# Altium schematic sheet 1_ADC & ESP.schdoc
size 307 x 218 mm; Symbol: Drawing-Symbol_A4; Device: Drawing-Symbol_A4; @Project Name: Bed Temp Regulation; @Page Count: 4; @Update Date: 2026-02-17; @Create Date: 2026-02-11; @Schematic Name: Schematic Main; @Page No: 1; @Page Name: ADC & ESP; Company: EasyEDA.com; Version: V1.0; Page Size: A4; @Create Time: 12:15:24; @Update Time: 20:09:26; Width: 1170; Height: 825; Region Start: 1; X Region Count: 6; Y Region Count: 4; Blade Width: 10; Title Block Position: 3; @Board Name: Main Board
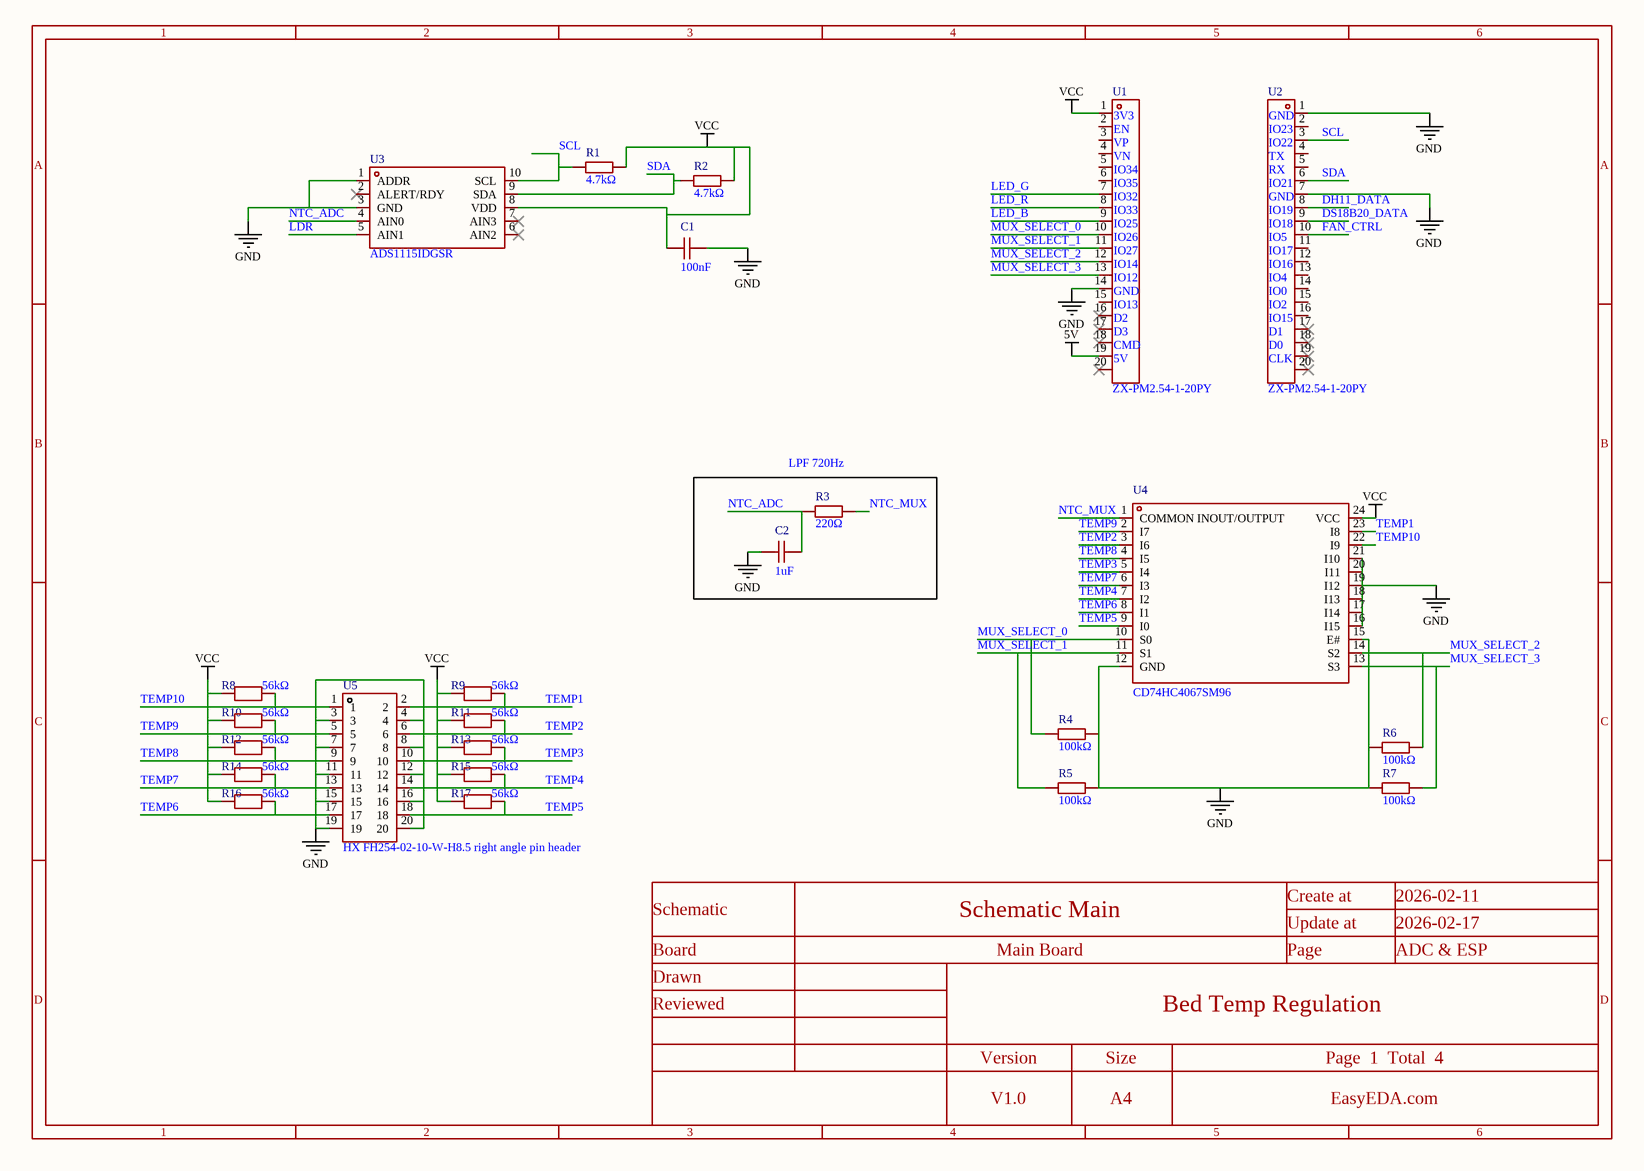
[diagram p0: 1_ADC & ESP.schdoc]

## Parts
C1  100nF  [C0805]
C2  1uF  [C0805]
R1  4.7kΩ  [R0805]
R2  4.7kΩ  [R0805]
R3  220Ω  [R0805]
R4  100kΩ  [R0805]
R5  100kΩ  [R0805]
R6  100kΩ  [R0805]
R7  100kΩ  [R0805]
R8  56kΩ  [R0805]
R9  56kΩ  [R0805]
R10  56kΩ  [R0805]
R11  56kΩ  [R0805]
R12  56kΩ  [R0805]
R13  56kΩ  [R0805]
R14  56kΩ  [R0805]
R15  56kΩ  [R0805]
R16  56kΩ  [R0805]
R17  56kΩ  [R0805]
U1  ZX-PM2.54-1-20PY  [HDR-TH_20P-P2.54-V-F]
U2  ZX-PM2.54-1-20PY  [HDR-TH_20P-P2.54-V-F]
U3  ADS1115IDGSR  [MSOP-10_L3.0-W3.0-P0.50-LS5.0-BL]
U4  CD74HC4067SM96  [SSOP-24_L8.1-W5.3-P0.65-LS7.8-BL]
U5  HX FH254-02-10-W-H8.5 right angle pin header  [HDR-TH_20P-P2.54-H-F-R2-C10-S2.54-W12.7]

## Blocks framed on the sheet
LPF 720Hz: C2 R3

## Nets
5V: U1.19
GND: C1.1 C2.1 R4.2 R5.2 R6.1 R7.1 U1.14 U2.1 U2.7 U3.1(ADDR) U3.3(GND) U4.12(GND) U4.15(E#) U4.16(I15) U4.17(I14) U4.18(I13) U4.19(I12) U4.20(I11) U4.21(I10) U5.3 U5.4 U5.7 U5.8 U5.11 U5.12 U5.15 U5.16 U5.19 U5.20
VCC: C1.2 R1.1 R2.2 R8.1 R9.1 R10.1 R11.1 R12.1 R13.1 R14.1 R15.1 R16.1 R17.1 U1.1 U3.8(VDD) U4.24(VCC)
DH11_DATA: U2.8
DS18B20_DATA: U2.9
FAN_CTRL: U2.10
LDR: U3.5(AIN1)
LED_B: U1.9
LED_G: U1.7
LED_R: U1.8
MUX_SELECT_0: R4.1 U1.10 U4.10(S0)
MUX_SELECT_1: R5.1 U1.11 U4.11(S1)
MUX_SELECT_2: R6.2 U1.12 U4.14(S2)
MUX_SELECT_3: R7.2 U1.13 U4.13(S3)
NTC_ADC: C2.2 R3.1 U3.4(AIN0)
NTC_MUX: R3.2 U4.1(COMMON_INOUT/OUTPUT)
SCL: R1.2 U2.3 U3.10(SCL)
SDA: R2.1 U2.6 U3.9(SDA)
TEMP1: R9.2 U4.23(I8) U5.2
TEMP2: R11.2 U4.3(I6) U5.6
TEMP3: R13.2 U4.5(I4) U5.10
TEMP4: R15.2 U4.7(I2) U5.14
TEMP5: R17.2 U4.9(I0) U5.18
TEMP6: R16.2 U4.8(I1) U5.17
TEMP7: R14.2 U4.6(I3) U5.13
TEMP8: R12.2 U4.4(I5) U5.9
TEMP9: R10.2 U4.2(I7) U5.5
TEMP10: R8.2 U4.22(I9) U5.1

Not connected (* = marked no-connect by the designer): U1 2 3 4 5 6 15 16* 17* 18* 20*; U2 2 4 5 11 12 13 14 15 16 17* 18* 19* 20*; U3 2(ALERT/RDY)* 6(AIN2)* 7(AIN3)*

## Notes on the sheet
- (near U1) 3V3
  EN
  VP
  VN
  IO34
  IO35
  IO32
  IO33
  IO25
  IO26
  IO27
  IO14
  IO12
  GND
  IO13
  D2
  D3
  CMD
  5V
- (near U2) GND
  IO23
  IO22
  TX
  RX
  IO21
  GND
  IO19
  IO18
  IO5
  IO17
  IO16
  IO4
  IO0
  IO2
  IO15
  D1
  D0
  CLK

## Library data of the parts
C1 = CL21B104KCFNNNE: Manufacturer: SAMSUNG(三星); Add into BOM: yes; Tolerance: ±10%; Voltage Rating: 100V; Temperature Coefficient: X7R
C2 = CL21B105KBFNNNE: Manufacturer: SAMSUNG(三星); Add into BOM: yes; Tolerance: ±10%; Voltage Rating: 50V; Temperature Coefficient: X7R
R1 R2 = 0805W8F4701T5E: Manufacturer: UNI-ROYAL(厚声); Add into BOM: yes; Tolerance: ±1%; Temperature Coefficient: ±100ppm/℃
R3 = 0805W8F2200T5E: Manufacturer: UNI-ROYAL(厚声); Add into BOM: yes; Tolerance: ±1%; Power(Watts): 125mW; Voltage-Supply(Max): 150V; Temperature Coefficient: ±100ppm/℃
R4-R7 = 0805W8F1003T5E: Manufacturer: UNI-ROYAL(厚声); Symbol: 0805W8F1003T5E_C149504; Add into BOM: yes; Tolerance: ±1%; Power(Watts): 125mW; Voltage-Supply(Max): 150V; Temperature Coefficient: ±100ppm/℃
R8-R17 = TC0525B5602T5G: Manufacturer: UNI-ROYAL(厚声); Add into BOM: yes; Tolerance: ±0.1%; Power(Watts): 125mW; Voltage-Supply(Max): 150V; Temperature Coefficient: ±25ppm/℃
U1 U2 = ZX-PM2.54-1-20PY: Manufacturer: Megastar(兆星); Add into BOM: yes; Holes Structure: 1x20P; Pitch: 2.54mm; Circular Hole / Square Hole: Square Hole; Number of Positions: 20P; Current Rating: 3A; Holes Direction: Top; PIN Length: 3.2mm
U3 = ADS1115IDGSR: Manufacturer: TI(德州仪器); Add into BOM: yes; Resolution(Bits): 16; number of channels: 2; Voltage - Supply: 2V~5.5V; Interface: I2C; Integral non - linearity: 1LSB; Clock/Oscillator: Built-in; Programmable Gain: Support; ADC architecture: Sigma-Delta; Data rate: 128Hz；8Hz；64Hz；16Hz；32Hz；250Hz；475Hz；860Hz; Quiescent Current (Iq): 500nA; Full-Scale Range(FSR): 2.048V
U4 = CD74HC4067SM96: Manufacturer: TI(德州仪器); Add into BOM: yes; Switch Circuit: 16:1; Number of Channels: 16; Voltage - Supply: 2V~6V; Ron: 70Ω; Con: 5pF; Bandwidth: 89MHz; Propagation Delay (tpd): 15ns
U5 = HX FH254-02-10-W-H8.5 right angle pin header: Manufacturer: hanxia(韩下); Add into BOM: yes; Holes Structure: 2x10P; Pitch: 2.54mm; Circular Hole / Square Hole: Square Hole; Number of Positions: 20P; Current Rating: 3A; Voltage Rating (Max): 1kV; Holes Direction: Side; PIN Length: 3.2mm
